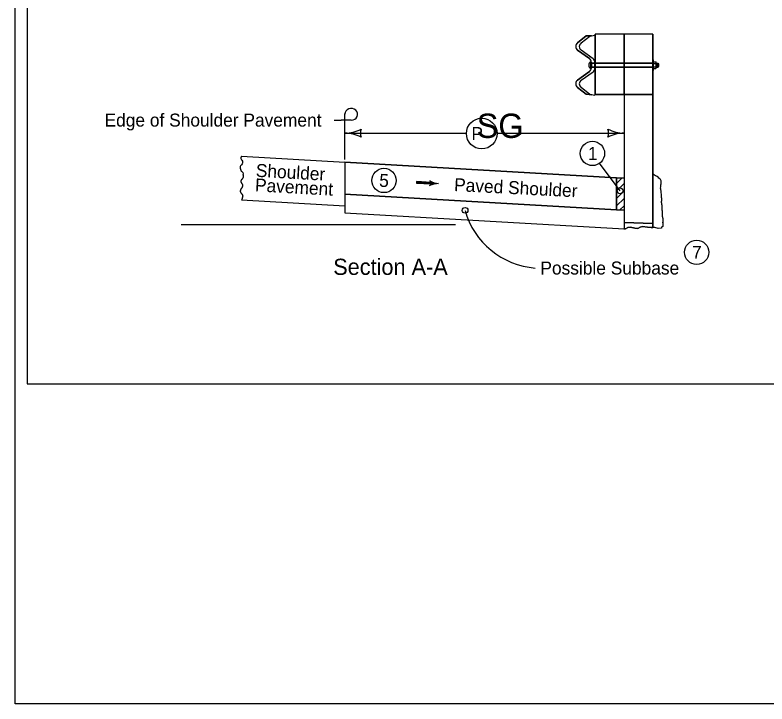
# Model space of a CAD drawing. Extents: x 9538 to 81668, y 7600 to 11751.
# Drawn here: x 20933 to 21860, y 7924 to 8774 of the extents above; entities that cross this region are included whole.
import ezdxf

# ---------------------------------------------------------------- set-up
doc = ezdxf.new("R2010")
doc.units = 0
for name, color, linetype in [('Default', 7, 'Continuous'), ('DsnShtMinorGrid13', 7, 'Continuous'), ('DsnShtMinorGrid14', 7, 'Continuous'), ('dsnStdCells', 7, 'Continuous'), ('dsnStdDimension', 7, 'Continuous'), ('dsnStdNameDate', 7, 'Continuous'), ('dsnStdNote', 7, 'Continuous'), ('dsnStdShading', 7, 'Continuous'), ('dsnStdTable', 7, 'Continuous')]:
    doc.layers.add(name, color=color, linetype=linetype)

msp = doc.modelspace()

# ---------------------------------------------------------------- linework, layer by layer
at = {"layer": 'Default'}
msp.add_lwpolyline([(20932.54, 9944.02), (24067.55, 9944.02), (24067.55, 7924.02), (20932.54, 7924.02)], close=True, dxfattribs=at)
at = {"layer": 'DsnShtMinorGrid13'}
for centre, radius in [((21644.81, 8603.28), 15), ((21387.6, 8569.91), 15), ((21678.93, 8557.17), 3.58), ((21773.4, 8481.26), 15)]:
    msp.add_circle(centre, radius, dxfattribs=at)
at = {"layer": 'DsnShtMinorGrid14'}
msp.add_circle((21487.63, 8533.07), 3.54, dxfattribs=at)
at = {"layer": 'dsnStdCells'}
for p, q in [((21626.57, 8730.73), (21641.08, 8720.31)), ((21641.08, 8704.24), (21626.57, 8693.82))]:
    msp.add_line(p, q, dxfattribs=at)
for points in [[(21630.83, 8739.63), (21630.81, 8739.62), (21641.59, 8748.02), (21643.47, 8748.36), (21637.14, 8748.24), (21626.38, 8739.85)], [(21683.87, 8714.93), (21683.87, 8750.61), (21648.32, 8750.61), (21648.32, 8714.93), (21648.32, 8714.93), (21683.87, 8714.93)], [(21719.41, 8714.93), (21719.41, 8718.93), (21719.41, 8750.61), (21683.87, 8750.61), (21683.87, 8714.93), (21719.41, 8714.93)], [(21645.53, 8720.09), (21645.56, 8720.07), (21630.99, 8730.53), (21631.02, 8730.51)], [(21643.48, 8715.68), (21643.48, 8714.6), (21647.93, 8714.6), (21647.93, 8715.46), (21647.92, 8715.46)], [(21647.92, 8708.65), (21647.93, 8708.65), (21647.93, 8709.93), (21643.48, 8709.93), (21643.48, 8708.87), (21643.48, 8709.93), (21643.48, 8709.93), (21643.48, 8708.87)], [(21648.32, 8714.6), (21648.32, 8709.93), (21648.33, 8709.93), (21683.87, 8709.93), (21683.87, 8714.6), (21648.32, 8714.6), (21648.32, 8714.6)], [(21648.32, 8709.6), (21648.32, 8675.96), (21683.87, 8675.96), (21683.87, 8709.6), (21648.32, 8709.6)], [(21719.41, 8709.93), (21719.41, 8714.6), (21683.87, 8714.6), (21683.87, 8709.93), (21719.41, 8709.93)], [(21719.41, 8675.96), (21719.41, 8705.6), (21719.41, 8709.6), (21683.87, 8709.6), (21683.87, 8675.96), (21719.41, 8675.96)], [(21631.02, 8693.6), (21630.99, 8693.58), (21645.56, 8704.04), (21645.53, 8704.02)], [(21626.38, 8684.7), (21637.14, 8676.31), (21644.25, 8675.62), (21641.59, 8676.09), (21630.81, 8684.5), (21630.83, 8684.48)], [(21719.41, 8517.01), (21719.41, 8675.96), (21683.87, 8675.96), (21683.87, 8572.99), (21683.87, 8566.3), (21683.87, 8566.3), (21683.87, 8566.3), (21683.87, 8557.07), (21683.87, 8557.07), (21683.87, 8557.07), (21683.87, 8547.93), (21683.87, 8547.93), (21683.87, 8547.93), (21683.87, 8541), (21683.87, 8518.17), (21719.41, 8517.01)], [(21719.41, 8517.01), (21683.87, 8518.17), (21683.87, 8510.15), (21685.51, 8510.38), (21688.26, 8511.97), (21691.55, 8512.5), (21697.16, 8510.91), (21700.87, 8510.69), (21703.52, 8512.5), (21706.6, 8513.13), (21712.85, 8512.39), (21717.09, 8511.97), (21719.41, 8511.97), (21719.41, 8517.01)]]:
    msp.add_lwpolyline(points, dxfattribs=at)
msp.add_lwpolyline([(21647.93, 8714.6), (21643.48, 8714.6), (21643.48, 8711.14), (21643.48, 8712.27), (21643.48, 8709.93), (21647.93, 8709.93)], close=True, dxfattribs=at)
for centre, start, end in [((21629.86, 8735.36), 127.75002, 234.69086), ((21634.3, 8735.14), 127.75002, 234.69086), ((21637.8, 8715.68), 0, 54.69099), ((21642.25, 8715.46), 0, 54.69099), ((21637.8, 8708.87), 305.30901, 0), ((21642.25, 8708.65), 305.30901, 0), ((21629.86, 8689.19), 125.30914, 232.24998), ((21634.3, 8688.97), 125.30914, 232.24998)]:
    msp.add_arc(centre, 5.68, start, end, dxfattribs=at)
at = {"layer": 'dsnStdDimension'}
for p, q in [((21339.48, 8628.24), (21489.31, 8628.24)), ((21527.16, 8628.4), (21683.87, 8628.4))]:
    msp.add_line(p, q, dxfattribs=at)
msp.add_circle((21508.24, 8627.84), 18.93, dxfattribs=at)
for centre, radius, start, end in [((21339.48, 8670.74), 42.5, 270, 298.07249), ((21339.48, 8585.74), 42.5, 61.92751, 90), ((21375.11, 8628.24), 16.42, 162.26665, 197.73335), ((21648.23, 8628.4), 16.42, 342.26665, 17.73335), ((21683.87, 8670.9), 42.5, 241.92751, 270), ((21683.87, 8585.9), 42.5, 90, 118.07249), ((21581.8, 8559.36), 97.76, 195.59781, 265.55799)]:
    msp.add_arc(centre, radius, start, end, dxfattribs=at)
at = {"layer": 'dsnStdNameDate'}
msp.add_line((21678.93, 8557.17), (21653.55, 8591.09), dxfattribs=at)
at = {"layer": 'dsnStdNote'}
for p, q in [((21339.48, 8631.56), (21339.48, 8652.42)), ((21326.11, 8644.41), (21334.79, 8644.41)), ((21347.29, 8644.41), (21334.79, 8644.41)), ((21339.48, 8595.62), (21339.48, 8631.56)), ((21445.86, 8566.52), (21427.66, 8567.57)), ((21445.76, 8565.58), (21445.76, 8565.58)), ((21445.87, 8567.53), (21445.87, 8567.53))]:
    msp.add_line(p, q, dxfattribs=at)
for points in [[(21445.89, 8567.46), (21427.72, 8568.51), (21427.59, 8566.63), (21445.76, 8565.58), (21445.81, 8567.19), (21427.94, 8568.29), (21427.88, 8566.79), (21445.38, 8565.84), (21445.5, 8566.96), (21428.17, 8568.02), (21428.15, 8567.02), (21445.16, 8566.04), (21445.26, 8566.75), (21428.36, 8567.8), (21428.35, 8567.24), (21444.95, 8566.31)], [(21445.48, 8568.72), (21446.18, 8567.55), (21446.16, 8565.9), (21445.4, 8564.51), (21448.15, 8565.37), (21451.35, 8566.02), (21452.25, 8566.16), (21450, 8566.7), (21446.78, 8567.93), (21445.83, 8568.47), (21445.95, 8564.95), (21450.9, 8566.17), (21446.26, 8567.75), (21446.28, 8565.33), (21449.67, 8566.26), (21446.67, 8567.12), (21446.44, 8565.74), (21448.6, 8566.24), (21447.01, 8566.75), (21446.88, 8566.09), (21447.66, 8566.25)]]:
    msp.add_lwpolyline(points, dxfattribs=at)
for centre, major_axis, start_param, end_param in [((21347.29, 8651.54), (-7.81, 0), 1.570796, 6.283185), ((21442.09, 8566.74), (3.88, 0), 5.202895, 7.237436), ((21454.36, 8545.74), (22.17, 0), 1.537172, 2.061295), ((21457.15, 8586.16), (-22.17, 0), 0.954258, 1.478381)]:
    msp.add_ellipse(centre, major_axis=major_axis, ratio=0.913811, start_param=start_param, end_param=end_param, dxfattribs=at)
at = {"layer": 'dsnStdShading'}
for p, q in [((20947.54, 9929.02), (20947.54, 8319.02)), ((20947.54, 8319.02), (24043.23, 8319.02))]:
    msp.add_line(p, q, dxfattribs=at)
at = {"layer": 'dsnStdTable'}
for p, q in [((21626.38, 8739.85), (21637.14, 8748.24)), ((21630.81, 8739.62), (21641.59, 8748.02)), ((21637.14, 8748.24), (21643.47, 8748.36)), ((21641.59, 8748.02), (21647.93, 8749.14)), ((21719.41, 8750.61), (21648.32, 8750.61)), ((21648.32, 8675.96), (21648.32, 8750.61)), ((21683.87, 8675.96), (21683.87, 8750.61)), ((21719.41, 8750.61), (21719.41, 8511.97)), ((21641.08, 8720.31), (21626.57, 8730.73)), ((21645.56, 8720.07), (21630.99, 8730.53)), ((21719.41, 8718.9), (21720.09, 8718.9)), ((21720.1, 8705.57), (21720.09, 8718.9)), ((21642.71, 8708.21), (21642.71, 8716.29)), ((21642.71, 8714.6), (21648.14, 8714.6)), ((21642.71, 8709.93), (21648.32, 8709.93)), ((21643.48, 8708.87), (21643.48, 8715.68)), ((21643.48, 8708.87), (21643.48, 8712.27)), ((21643.48, 8712.27), (21643.48, 8708.87)), ((21643.65, 8714.6), (21648.32, 8714.6)), ((21647.93, 8712.06), (21647.93, 8715.46)), ((21647.93, 8708.65), (21647.93, 8712.06)), ((21647.93, 8712.06), (21647.93, 8708.65)), ((21648.32, 8714.93), (21719.41, 8714.93)), ((21648.32, 8714.6), (21719.41, 8714.6)), ((21648.32, 8709.6), (21719.41, 8709.6)), ((21648.33, 8709.93), (21719.41, 8709.93)), ((21720.09, 8714.26), (21723.06, 8714.26)), ((21720.09, 8710.22), (21723.06, 8710.22)), ((21720.1, 8716.28), (21723.06, 8716.28)), ((21723.43, 8709.21), (21723.43, 8715.27)), ((21723.43, 8714.57), (21725.8, 8714.57)), ((21723.43, 8709.9), (21725.8, 8709.9)), ((21724.32, 8714.57), (21724.32, 8709.9)), ((21725.06, 8714.57), (21725.06, 8709.9)), ((21725.8, 8714.57), (21726.24, 8714.04)), ((21725.8, 8714.57), (21725.8, 8709.9)), ((21726.24, 8710.44), (21725.8, 8709.9)), ((21726.24, 8714.04), (21726.24, 8710.44)), ((21626.57, 8693.82), (21641.08, 8704.24)), ((21630.99, 8693.58), (21645.56, 8704.04)), ((21719.41, 8705.57), (21720.1, 8705.57)), ((21720.09, 8708.2), (21723.06, 8708.2)), ((21637.14, 8676.31), (21626.38, 8684.7)), ((21641.59, 8676.09), (21630.81, 8684.5)), ((21644.25, 8675.62), (21637.14, 8676.31)), ((21647.93, 8674.97), (21641.59, 8676.09)), ((21683.87, 8675.96), (21648.32, 8675.96)), ((21683.87, 8675.96), (21683.87, 8509.43)), ((21211.86, 8599.9), (21339.48, 8592.48)), ((21339.48, 8592.48), (21339.48, 8538.47)), ((21339.48, 8592.48), (21674.61, 8572.99)), ((21674.61, 8572.99), (21339.48, 8592.48)), ((21339.48, 8592.48), (21339.48, 8552.88)), ((21674.61, 8566.25), (21681.36, 8572.99)), ((21674.61, 8566.25), (21681.36, 8572.99)), ((21674.61, 8566.25), (21681.36, 8572.99)), ((21674.61, 8566.25), (21681.36, 8572.99)), ((21674.61, 8572.99), (21683.85, 8572.99)), ((21674.61, 8572.99), (21674.61, 8533.56)), ((21674.61, 8533.56), (21674.61, 8572.99)), ((21674.61, 8557.06), (21683.85, 8566.3)), ((21674.61, 8557.06), (21683.85, 8566.3)), ((21674.61, 8557.06), (21683.85, 8566.3)), ((21674.61, 8557.06), (21683.85, 8566.3)), ((21729.46, 8566.23), (21729.46, 8566.23)), ((21674.61, 8533.56), (21339.48, 8552.88)), ((21339.48, 8552.88), (21674.61, 8533.56)), ((21674.61, 8547.84), (21683.85, 8557.07)), ((21674.61, 8547.84), (21683.85, 8557.07)), ((21674.61, 8547.84), (21683.85, 8557.07)), ((21674.61, 8547.84), (21683.85, 8557.07)), ((21212.04, 8545.88), (21339.48, 8538.47)), ((21674.61, 8538.61), (21683.85, 8547.84)), ((21339.48, 8538.47), (21339.48, 8530.05)), ((21674.61, 8533.56), (21683.85, 8533.56)), ((21678.71, 8533.56), (21683.85, 8538.7)), ((21339.48, 8530.05), (21683.87, 8510.19)), ((21137.42, 8515.64), (21475.92, 8515.64))]:
    msp.add_line(p, q, dxfattribs=at)
for points in [[(21723.41, 8709.53), (21723.37, 8709.8), (21723.32, 8709.97), (21723.23, 8710.13), (21723.12, 8710.22), (21723.19, 8710.32), (21723.28, 8710.54), (21723.34, 8710.85), (21723.42, 8711.6), (21723.41, 8709.53), (21723.39, 8709.67), (21723.35, 8709.88), (21723.27, 8710.09), (21723.16, 8710.21), (21723.2, 8710.29), (21723.26, 8710.44), (21723.36, 8710.94), (21723.4, 8711.32), (21723.39, 8709.72), (21723.37, 8709.84), (21723.32, 8710), (21723.19, 8710.21), (21723.25, 8710.38), (21723.32, 8710.71), (21723.38, 8711.04), (21723.37, 8709.87), (21723.33, 8710), (21723.22, 8710.2), (21723.27, 8710.41), (21723.32, 8710.67), (21723.36, 8710.84), (21723.35, 8709.98), (21723.29, 8710.09), (21723.25, 8710.2), (21723.34, 8710.66), (21723.33, 8710.06), (21723.27, 8710.2), (21723.31, 8710.49), (21723.31, 8710.14), (21723.28, 8710.21), (21723.29, 8710.31), (21723.29, 8710.23)], [(21723.13, 8714.26), (21723.2, 8714.3), (21723.27, 8714.41), (21723.35, 8714.63), (21723.41, 8714.91), (21723.41, 8712.97), (21723.36, 8713.48), (21723.3, 8713.85), (21723.19, 8714.17), (21723.13, 8714.26), (21723.18, 8714.27), (21723.29, 8714.41), (21723.37, 8714.64), (21723.4, 8714.79), (21723.4, 8713.26), (21723.32, 8713.75), (21723.27, 8714.01), (21723.16, 8714.24), (21723.2, 8714.25), (21723.33, 8714.47), (21723.37, 8714.62), (21723.38, 8713.51), (21723.19, 8714.23), (21723.35, 8714.5), (21723.36, 8713.65), (21723.21, 8714.21), (21723.34, 8714.43), (21723.34, 8713.79), (21723.23, 8714.2), (21723.32, 8714.37), (21723.32, 8713.96), (21723.25, 8714.18), (21723.3, 8714.3), (21723.31, 8714.09), (21723.27, 8714.17), (21723.29, 8714.21)], [(21729.93, 8542.38), (21729.88, 8542.11), (21729.88, 8541.92), (21729.88, 8541.72), (21729.88, 8541.53), (21729.88, 8541.33), (21729.88, 8541.14), (21729.88, 8540.84), (21729.88, 8540.65), (21729.97, 8540.35), (21730.07, 8540.06), (21730.27, 8539.87), (21730.27, 8539.67), (21730.36, 8539.47), (21730.36, 8539.28), (21730.36, 8539.08), (21730.46, 8538.99), (21730.46, 8538.79), (21730.46, 8538.59), (21730.46, 8538.4), (21730.46, 8538.2), (21730.46, 8538.01), (21730.46, 8537.72), (21730.46, 8537.42), (21730.46, 8537.23), (21730.46, 8536.93), (21730.46, 8536.74), (21730.46, 8536.54), (21730.56, 8536.45), (21730.56, 8536.25), (21730.56, 8536.05), (21730.56, 8535.86), (21730.56, 8535.66), (21730.56, 8535.47), (21730.56, 8535.27), (21730.56, 8535.08), (21730.56, 8534.88), (21730.56, 8534.69), (21730.56, 8534.49), (21730.56, 8534.3), (21730.56, 8534.1), (21730.56, 8533.91), (21730.56, 8533.71), (21730.56, 8533.51), (21730.56, 8533.32), (21730.56, 8533.12), (21730.56, 8532.93), (21730.66, 8532.83), (21730.66, 8532.63), (21730.66, 8532.44), (21730.76, 8532.34), (21730.76, 8532.15), (21730.76, 8531.95), (21730.85, 8531.85), (21730.85, 8531.66), (21730.85, 8531.46), (21730.85, 8531.27), (21730.85, 8530.97), (21730.95, 8530.68), (21730.95, 8530.49), (21730.95, 8530.29), (21730.95, 8530.09), (21730.95, 8529.9), (21730.95, 8529.7), (21730.95, 8529.51), (21730.95, 8529.31), (21730.95, 8529.12), (21730.95, 8528.92), (21730.95, 8528.73), (21730.95, 8528.53), (21730.95, 8528.34), (21730.95, 8528.14), (21730.95, 8527.95), (21730.95, 8527.75), (21730.95, 8527.55), (21730.95, 8527.36), (21730.95, 8527.16), (21730.95, 8526.97), (21730.95, 8526.77), (21730.95, 8526.58), (21730.95, 8526.38), (21730.95, 8526.19), (21730.95, 8525.99), (21730.95, 8525.8), (21730.95, 8525.6), (21730.95, 8525.4), (21730.95, 8525.21), (21730.95, 8525.01), (21731.05, 8524.92), (21731.05, 8524.62), (21731.05, 8524.43), (21731.15, 8524.23), (21731.24, 8523.94), (21731.24, 8523.74), (21731.34, 8523.65), (21731.34, 8523.45), (21731.44, 8523.35), (21731.54, 8523.26), (21731.54, 8523.06), (21731.54, 8522.86), (21731.54, 8522.67), (21731.63, 8522.57), (21731.63, 8522.38), (21731.63, 8522.18), (21731.63, 8521.99), (21731.63, 8521.79), (21731.63, 8521.59), (21731.63, 8521.4), (21731.63, 8521.2), (21731.63, 8521.01), (21731.63, 8520.81), (21731.63, 8520.62), (21731.63, 8520.42), (21731.63, 8520.23), (21731.63, 8520.03), (21731.63, 8519.84), (21731.63, 8519.64), (21731.63, 8519.44), (21731.63, 8519.25), (21731.63, 8519.05), (21731.63, 8518.86), (21731.63, 8518.66), (21731.63, 8518.47), (21731.63, 8518.27), (21731.63, 8518.08), (21731.63, 8517.88), (21731.63, 8517.69), (21731.63, 8517.69), (21731.63, 8517.98), (21731.63, 8518.17), (21731.63, 8518.37), (21731.63, 8518.17), (21731.63, 8517.98), (21731.63, 8517.78), (21731.63, 8517.59), (21731.63, 8517.39), (21731.63, 8517.2), (21731.63, 8517), (21731.63, 8516.81), (21731.63, 8516.61), (21731.63, 8516.42), (21731.63, 8516.22), (21731.63, 8516.03), (21731.63, 8515.83), (21731.63, 8515.63), (21731.63, 8515.44), (21731.54, 8515.34), (21731.54, 8515.15), (21731.54, 8514.95), (21731.54, 8514.76), (21731.54, 8514.56), (21731.54, 8514.36), (21731.54, 8514.17), (21731.54, 8513.97), (21731.54, 8513.78), (21731.54, 8513.58), (21731.54, 8513.39), (21731.44, 8513.29), (21731.34, 8513.09), (21731.24, 8513), (21731.15, 8512.9), (21731.05, 8512.8), (21730.85, 8512.7), (21730.66, 8512.7), (21730.56, 8512.61), (21730.46, 8512.51), (21730.36, 8512.41), (21730.17, 8512.31), (21730.07, 8512.21), (21730.07, 8512.02), (21729.97, 8511.92), (21729.97, 8511.73), (21729.97, 8511.53), (21729.97, 8511.34), (21729.97, 8511.14), (21729.97, 8511.04), (21729.97, 8511.24)], [(21729.93, 8510.92), (21725.78, 8510.8), (21721.65, 8511.97), (21717.09, 8511.97), (21712.85, 8512.39), (21706.6, 8513.13), (21703.52, 8512.5), (21700.87, 8510.69), (21697.16, 8510.91), (21691.55, 8512.5), (21688.26, 8511.97), (21685.51, 8510.38), (21683.87, 8510.15)]]:
    msp.add_lwpolyline(points, dxfattribs=at)
msp.add_circle((21387.6, 8569.91), 15, dxfattribs=at)
for centre, radius, start, end in [((21629.86, 8735.36), 5.68, 127.75002, 234.69086), ((21634.3, 8735.14), 5.68, 127.75002, 234.69086), ((21637.8, 8715.68), 5.68, 360, 54.69099), ((21642.25, 8715.46), 5.68, 360, 54.69099), ((21644.78, 8712.26), 4.54, 117.20289, 242.8461), ((21637.8, 8708.87), 5.68, 305.30901, 0), ((21642.25, 8708.65), 5.68, 305.30901, 0), ((21629.86, 8689.19), 5.68, 125.30914, 232.24998), ((21634.3, 8688.97), 5.68, 125.30914, 232.24998)]:
    msp.add_arc(centre, radius, start, end, dxfattribs=at)
for centre in [(21723.06, 8715.27), (21723.06, 8709.21)]:
    msp.add_ellipse(centre, major_axis=(0, -1.01), ratio=0.362258, start_param=6.283156, end_param=9.424748, dxfattribs=at)
for points in [[(21211.86, 8599.9), (21211.36, 8596.3), (21212.4, 8594.79), (21213.27, 8592.5), (21212.66, 8590.44), (21210.75, 8588.06), (21210.23, 8586.16), (21210.75, 8583.87), (21211.62, 8581.49), (21212.66, 8580.78), (21214.04, 8578.24), (21214.04, 8577.4)], [(21212.07, 8560.29), (21212.28, 8560.54), (21212.48, 8560.8), (21212.83, 8561.36), (21213.12, 8561.95), (21213.23, 8562.26), (21213.33, 8562.57), (21213.46, 8563.19), (21213.51, 8563.81), (21213.47, 8564.4), (21213.41, 8564.68), (21213.37, 8564.81), (21213.32, 8564.94), (21213.12, 8565.32), (21212.83, 8565.68), (21212.53, 8566.05), (21212.28, 8566.45), (21212.14, 8566.73), (21212.01, 8567.01), (21211.75, 8567.59), (21211.54, 8568.15), (21211.47, 8568.45), (21211.42, 8568.74), (21211.41, 8568.87), (21211.41, 8569), (21211.56, 8569.77), (21211.77, 8570.29), (21212.02, 8570.8), (21212.47, 8571.44), (21212.99, 8571.98), (21213.5, 8572.53), (21213.73, 8572.84), (21213.93, 8573.18), (21214.14, 8573.65), (21214.29, 8574.13), (21214.4, 8574.6), (21214.43, 8574.84), (21214.44, 8574.96), (21214.45, 8575.08), (21214.4, 8575.59), (21214.25, 8576.1), (21214.2, 8576.23), (21214.14, 8576.35), (21214.1, 8576.48), (21214.07, 8576.61), (21214.04, 8577.4)], [(21729.93, 8542.38), (21730.26, 8545.29), (21730.03, 8550.15), (21729.59, 8555.9), (21728.93, 8560.33), (21729.15, 8563.64), (21729.59, 8567.84), (21728.93, 8570.94), (21726.72, 8572.93), (21724.73, 8574.7), (21722.52, 8575.81), (21720.31, 8577.13), (21719.42, 8577.8)], [(21212.07, 8560.29), (21211.86, 8560.06), (21211.61, 8559.82), (21211.37, 8559.58), (21211.19, 8559.31), (21211.05, 8559.03), (21210.91, 8558.74), (21210.65, 8558.17), (21210.54, 8557.89), (21210.45, 8557.6), (21210.38, 8557.31), (21210.35, 8557.16), (21210.33, 8557.01), (21210.34, 8556.5), (21210.47, 8555.98), (21210.68, 8555.46), (21210.93, 8554.95), (21211.38, 8554.32), (21211.9, 8553.77), (21212.41, 8553.22), (21212.64, 8552.92), (21212.84, 8552.58), (21213.24, 8551.63), (21213.35, 8551.16), (21213.36, 8550.68), (21213.32, 8550.39), (21213.28, 8550.1), (21213.22, 8549.81), (21213.15, 8549.53), (21212.84, 8548.38), (21212.66, 8547.77), (21212.47, 8547.17), (21212.24, 8546.58), (21212.11, 8546.29), (21211.97, 8546.01), (21211.89, 8545.89)]]:
    msp.add_spline(points, degree=3, dxfattribs=at)

# ---------------------------------------------------------------- texts
at = {"layer": 'DsnShtMinorGrid13'}
for s, p in [('1', (21639.18, 8595.28)), ('7', (21767.69, 8473.26))]:
    msp.add_text(s, height=16, dxfattribs=at).set_placement(p)
msp.add_text('5', height=16, rotation=356.69973, dxfattribs=at).set_placement((21381.38, 8562.26))
at = {"layer": 'dsnStdDimension'}
for s, height, p in [('SG', 30, (21501.95, 8622.4)), ('P', 16, (21495.52, 8619.84))]:
    msp.add_text(s, height=height, dxfattribs=at).set_placement(p)
at = {"layer": 'dsnStdNote'}
for s, height, p in [('Edge of Shoulder Pavement', 16, (21042.94, 8636.41)), ('Section A-A', 20, (21325.05, 8453.39)), ('Possible Subbase', 16, (21580.58, 8453.89))]:
    msp.add_text(s, height=height, dxfattribs=at).set_placement(p)
for s, rotation, p in [('Shoulder', 356.73462, (21229.23, 8574.55)), ('Pavement', 356.73462, (21228.21, 8556.58)), ('Paved Shoulder ', 357.0678, (21473.87, 8556.89))]:
    msp.add_text(s, height=16, rotation=rotation, dxfattribs=at).set_placement(p)

doc.saveas('drawing.dxf')
